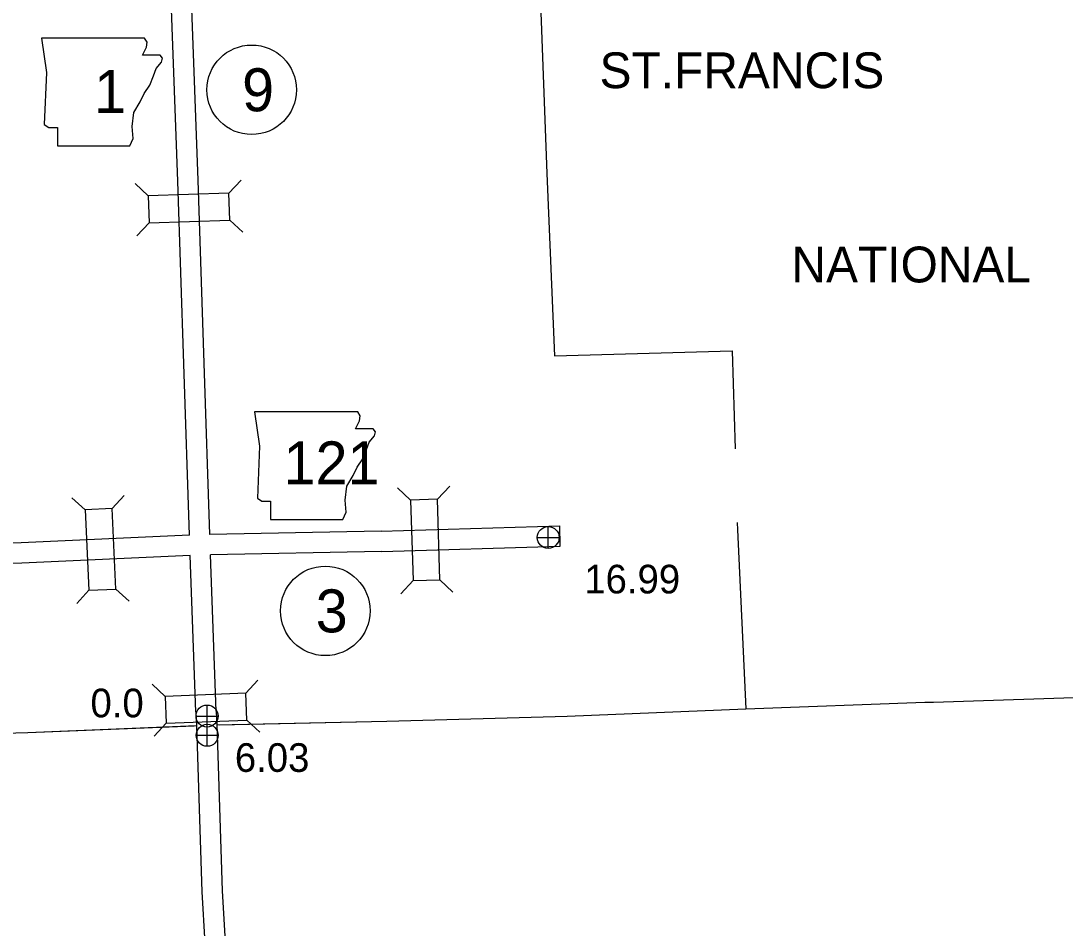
# Model space of a CAD drawing. Extents: x -939622 to -934222, y 1383701 to 1385301.
# Drawn here: x -935782 to -935735.82, y 1384106.09 to 1384146.23 of the extents above; entities that cross this region are included whole.
import ezdxf

# ---------------------------------------------------------------- set-up
doc = ezdxf.new("R2010")
doc.units = 0
for name, color, linetype in [('Level 10', 7, 'Continuous'), ('Level 2', 7, 'Continuous'), ('Level 20', 7, 'Continuous'), ('Level 21', 7, 'Continuous'), ('Level 25', 7, 'Continuous'), ('Level 26', 7, 'Continuous'), ('Level 27', 7, 'Continuous'), ('Level 8', 7, 'Continuous')]:
    doc.layers.add(name, color=color, linetype=linetype)

msp = doc.modelspace()

# ---------------------------------------------------------------- linework, layer by layer
at = {"layer": 'Level 10'}
for points in [[(-935774.547, 1384123.471), (-935774.788, 1384131.051), (-935775.054, 1384139.145), (-935775.353, 1384147.15), (-935775.575, 1384155.194), (-935775.787, 1384161.148), (-935775.795, 1384161.271), (-935775.799, 1384161.32), (-935775.803, 1384161.348), (-935775.812, 1384161.383), (-935775.824, 1384161.445), (-935775.833, 1384161.488), (-935775.863, 1384161.604), (-935775.895, 1384161.756), (-935775.914, 1384161.844), (-935775.937, 1384161.952), (-935775.97, 1384162.067), (-935775.99, 1384162.198), (-935776.035, 1384162.426), (-935776.068, 1384162.604), (-935776.065, 1384162.737), (-935776.085, 1384162.878), (-935776.304, 1384170.996), (-935776.376, 1384173.832)], [(-935773.648, 1384123.5), (-935773.888, 1384131.08), (-935774.155, 1384139.177), (-935774.453, 1384147.179), (-935774.676, 1384155.222), (-935774.888, 1384161.195), (-935774.898, 1384161.342), (-935774.905, 1384161.425), (-935774.918, 1384161.516), (-935774.933, 1384161.576), (-935774.943, 1384161.629), (-935774.957, 1384161.692), (-935774.986, 1384161.808), (-935775.015, 1384161.943), (-935775.034, 1384162.034), (-935775.064, 1384162.17), (-935775.089, 1384162.257), (-935775.103, 1384162.353), (-935775.151, 1384162.596), (-935775.166, 1384162.675), (-935775.163, 1384162.789), (-935775.186, 1384162.954), (-935775.404, 1384171.019), (-935775.476, 1384173.855)], [(-935766.066, 1384123.654), (-935773.648, 1384123.5)], [(-935766.07, 1384123.654), (-935758.171, 1384123.893)], [(-935758.144, 1384122.993), (-935758.171, 1384123.893)], [(-935774.547, 1384123.471), (-935781.984, 1384123.139), (-935790.06, 1384122.874), (-935797.92, 1384122.61), (-935799.671, 1384122.547), (-935805.892, 1384122.401), (-935813.871, 1384122.204), (-935821.814, 1384121.921)], [(-935766.048, 1384122.754), (-935773.617, 1384122.601)], [(-935766.043, 1384122.754), (-935758.144, 1384122.993)], [(-935774.516, 1384122.572), (-935781.949, 1384122.24), (-935790.03, 1384121.975), (-935797.889, 1384121.711), (-935799.644, 1384121.648), (-935805.87, 1384121.502), (-935813.844, 1384121.305), (-935821.781, 1384121.022)], [(-935774.257, 1384115.661), (-935774.516, 1384122.572)], [(-935773.357, 1384115.695), (-935773.617, 1384122.601)], [(-935774.257, 1384115.663), (-935774.237, 1384115.052)], [(-935773.357, 1384115.693), (-935773.337, 1384115.08)], [(-935774.237, 1384115.055), (-935773.997, 1384107.704), (-935773.868, 1384105.431)], [(-935773.338, 1384115.111), (-935773.098, 1384107.744), (-935772.969, 1384105.482)]]:
    msp.add_lwpolyline(points, dxfattribs=at)
at = {"layer": 'Level 2'}
for points in [[(-935765.818, 1384115.242), (-935757.845, 1384115.475), (-935749.948, 1384115.795), (-935742.028, 1384116.089), (-935741.65, 1384116.089), (-935734.115, 1384116.338), (-935733.852, 1384116.356), (-935726.158, 1384116.664), (-935726.03, 1384116.679), (-935718.342, 1384116.857), (-935714.154, 1384116.916), (-935710.216, 1384117.032)], [(-935765.818, 1384115.242), (-935757.845, 1384115.475), (-935749.948, 1384115.795), (-935742.028, 1384116.089), (-935741.65, 1384116.089), (-935734.115, 1384116.338), (-935733.852, 1384116.356), (-935726.158, 1384116.664), (-935726.03, 1384116.679), (-935718.342, 1384116.857), (-935714.154, 1384116.916), (-935710.216, 1384117.032)], [(-935797.118, 1384114.304), (-935789.737, 1384114.523), (-935781.692, 1384114.748), (-935774.237, 1384115.052)], [(-935797.024, 1384114.306), (-935789.737, 1384114.523), (-935781.692, 1384114.748), (-935774.341, 1384115.048)], [(-935773.337, 1384115.08), (-935765.818, 1384115.242)], [(-935773.232, 1384115.083), (-935765.818, 1384115.242)]]:
    msp.add_lwpolyline(points, dxfattribs=at)
at = {"layer": 'Level 20'}
for p, q in [((-935776.365, 1384138.487), (-935776.944, 1384139.029)), ((-935772.803, 1384138.605), (-935772.262, 1384139.183)), ((-935776.326, 1384137.3), (-935776.868, 1384136.722)), ((-935772.764, 1384137.417), (-935772.186, 1384136.876)), ((-935764.765, 1384125.026), (-935765.342, 1384125.569)), ((-935763.578, 1384125.062), (-935763.035, 1384125.639)), ((-935779.154, 1384124.598), (-935779.739, 1384125.131)), ((-935777.967, 1384124.653), (-935777.433, 1384125.238)), ((-935764.658, 1384121.464), (-935765.201, 1384120.887)), ((-935763.47, 1384121.5), (-935762.894, 1384120.957)), ((-935778.987, 1384121.037), (-935779.521, 1384120.452)), ((-935777.801, 1384121.093), (-935777.215, 1384120.559)), ((-935775.615, 1384116.346), (-935776.196, 1384116.885)), ((-935772.054, 1384116.48), (-935771.515, 1384117.06)), ((-935772.009, 1384115.293), (-935771.428, 1384114.754)), ((-935775.571, 1384115.159), (-935776.109, 1384114.578))]:
    msp.add_line(p, q, dxfattribs=at)
for points in [[(-935776.326, 1384137.3), (-935772.764, 1384137.417), (-935772.803, 1384138.605), (-935776.365, 1384138.487)], [(-935763.47, 1384121.5), (-935763.578, 1384125.062), (-935764.765, 1384125.026), (-935764.658, 1384121.464)], [(-935777.801, 1384121.093), (-935777.967, 1384124.653), (-935779.154, 1384124.598), (-935778.987, 1384121.037)], [(-935775.571, 1384115.159), (-935772.009, 1384115.293), (-935772.054, 1384116.48), (-935775.615, 1384116.346)]]:
    msp.add_lwpolyline(points, close=True, dxfattribs=at)
at = {"layer": 'Level 21'}
for points in [[(-935781.088, 1384145.472), (-935780.86, 1384143.95), (-935780.962, 1384141.64), (-935780.759, 1384141.513), (-935780.378, 1384141.513), (-935780.378, 1384140.701), (-935777.18, 1384140.701), (-935777.028, 1384141.031), (-935777.079, 1384141.564), (-935777.003, 1384142.173), (-935776.724, 1384142.655), (-935776.546, 1384143.011), (-935776.292, 1384143.391), (-935776.14, 1384143.797), (-935776.013, 1384144.127), (-935775.785, 1384144.406), (-935775.734, 1384144.584), (-935775.835, 1384144.711), (-935776.622, 1384144.711), (-935776.445, 1384145.066), (-935776.419, 1384145.295), (-935776.524, 1384145.47)], [(-935771.667, 1384128.94), (-935771.439, 1384127.417), (-935771.541, 1384125.108), (-935771.338, 1384124.981), (-935770.957, 1384124.981), (-935770.957, 1384124.169), (-935767.759, 1384124.169), (-935767.607, 1384124.499), (-935767.658, 1384125.032), (-935767.582, 1384125.641), (-935767.303, 1384126.123), (-935767.125, 1384126.479), (-935766.871, 1384126.859), (-935766.719, 1384127.265), (-935766.592, 1384127.595), (-935766.364, 1384127.874), (-935766.313, 1384128.052), (-935766.414, 1384128.179), (-935767.201, 1384128.179), (-935767.024, 1384128.534), (-935766.998, 1384128.762), (-935767.103, 1384128.938)]]:
    msp.add_lwpolyline(points, close=True, dxfattribs=at)
at = {"layer": 'Level 26'}
for p, q in [((-935758.681, 1384122.886), (-935758.681, 1384123.861)), ((-935759.169, 1384123.374), (-935758.194, 1384123.374)), ((-935773.764, 1384114.985), (-935773.764, 1384115.96)), ((-935774.252, 1384115.473), (-935773.277, 1384115.473)), ((-935773.759, 1384114.138), (-935773.759, 1384115.113)), ((-935774.247, 1384114.626), (-935773.272, 1384114.626))]:
    msp.add_line(p, q, dxfattribs=at)
for centre in [(-935758.681, 1384123.374), (-935773.764, 1384115.473), (-935773.759, 1384114.626)]:
    msp.add_circle(centre, 0.487, dxfattribs=at)
at = {"layer": 'Level 27'}
for centre in [(-935771.791, 1384143.182), (-935768.535, 1384120.127)]:
    msp.add_circle(centre, 1.98, dxfattribs=at)
at = {"layer": 'Level 8'}
for points in [[(-935759.546, 1384164.487), (-935759.493, 1384163.448), (-935759.421, 1384155.33), (-935759.03, 1384147.413), (-935758.74, 1384139.475), (-935758.4, 1384131.409), (-935750.548, 1384131.629), (-935750.418, 1384127.293)], [(-935750.32, 1384124.03), (-935750.31, 1384123.707), (-935749.948, 1384115.795)]]:
    msp.add_lwpolyline(points, dxfattribs=at)

# ---------------------------------------------------------------- texts
at = {"layer": 'Level 21'}
for s, height, p in [('1', 1.901, (-935778.759, 1384142.158)), ('121', 1.9008, (-935770.381, 1384125.724))]:
    msp.add_text(s, height=height, dxfattribs=at).set_placement(p)
at = {"layer": 'Level 25'}
for s, p in [('16.99', (-935757.086, 1384120.899)), ('0.0', (-935778.919, 1384115.418)), ('6.03', (-935772.537, 1384113.004))]:
    msp.add_text(s, height=1.2672, dxfattribs=at).set_placement(p)
at = {"layer": 'Level 27'}
for s, p in [('9', (-935772.216, 1384142.231)), ('3', (-935768.96, 1384119.176))]:
    msp.add_text(s, height=1.901, dxfattribs=at).set_placement(p)
at = {"layer": 'Level 8'}
for s, p in [('ST.FRANCIS', (-935756.411, 1384143.252)), ('NATIONAL', (-935747.924, 1384134.659))]:
    msp.add_text(s, height=1.584, dxfattribs=at).set_placement(p)

doc.saveas('drawing.dxf')
